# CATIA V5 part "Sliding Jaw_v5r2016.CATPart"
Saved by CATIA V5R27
Part number: Sliding Jaw
Bounding box of the stored display mesh (mm): x -32 to 32, y -16 to 16, z -9 to 36
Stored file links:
  E:\_Deepak\2017_Deepak\CATIA\Resources\Tutorial Files\Tutorials\c13_catia_v5_6r2016_tut\c13tut2\c13tut02.CATParts\Sliding Jaw_v5r2016.CATPart
  C:\Program Files\Dassault Systemes\B09\intel_a\reffiles\standard\MetricThickPitch.txt
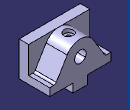
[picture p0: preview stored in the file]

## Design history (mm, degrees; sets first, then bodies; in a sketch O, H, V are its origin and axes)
Body1 (main body)
  Sketch1 on xy-plane, origin (0, 0, 0), H (1, 0, 0), V (0, 1, 0)
    line L1 (-32, -16) -> (32, -16)
    line L2 (32, -16) -> (32, 16)
    line L3 (32, 16) -> (-32, 16)
    line L4 (-32, 16) -> (-32, -16)
    distance H L1 = 16
    distance V L4 = 32
    length L4 = 32
    length L1 = 64
    horizontal: L1 H, L3 H
    vertical: L2 V, L4 V
  Pad1: profile Sketch1, direction (0, 0, 1), length 8
  Sketch2 on face of Pad1, origin (0, -16, 0), H (1, 0, 0), V (0, 0, 1)
    point P1 (-32, 0)
    line L1 (-32, 0) -> (32, 0)
    line L2 (32, 0) -> (32, 36)
    line L3 (32, 36) -> (-32, 36)
    line L4 (-32, 36) -> (-32, 0)
    reference projected line E1 (32, 0) -> (32, 8) from edge of Pad1
    reference projected line E2 (-32, 8) -> (-32, 0) from edge of Pad1
    length L2 = 36
    coincidence: P1 H, L2 E1, L4 E2
    horizontal: L1 H, L3 H
    vertical: L2 V, L4 V
  Pad2: profile Sketch2, direction (0, 1, 0), length 10
  Sketch3 on face of Pad1, origin (0, 16, 0), H (-1, 0, 0), V (0, 0, 1)
    arc A1 centre (0, 20) radius 16 from (13.6777, 28.3018) to (-13.6777, 28.3018) ccw
    point P1 (0, 20)
    reference projected line E1 (-32, 36) -> (32, 36) from edge of Pad2
    line L1 (-26, 8) -> (-13.6777, 28.3018)
    point P2 (-26, 8)
    line L2 (13.6777, 28.3018) -> (26, 8)
    point P3 (26, 8)
    reference projected line E2 (32, 8) -> (-32, 8) from edge of Pad1
    reference projected line E3 (32, 8) -> (-32, 8) from edge of Pad1
    line L3 (-26, 8) -> (26, 8)
    radius A1 = 16
    length L3 = 52
    distance V P3 = 26
    coincidence: P1 V, E2 P2, E3 P3
    tangency: A1 E1, L2 A1, L1 A1
    horizontal: L3 H
  Pad3: profile Sketch3, direction (0, -1, 0), up to the existing solid (limit type 2)
  Fillet1: radius 3, on 2 edges
  Sketch4 on face of Pad1, origin (-2.6964, 16, 22.8197), H (1, 0, 0), V (0, 0, -1)
    point P1 (2.6964, 2.8197)
    reference projected arc E1 centre (2.6964, 2.8197) radius 16 from (-10.9814, -5.4821) to (16.3741, -5.4821) ccw from edge of Pad3
    concentricity: P1 E1
  Hole1: placed by Sketch4, at (0, 16, 20) direction (0, -1, 0), diameter 12, depth 22, V-bottom angle 120
  Sketch5 on face of Pad1, origin (0, 16, 0), H (-1, 0, 0), V (0, 0, 1)
    point P1 (-7.75, 0)
    line L1 (-7.75, 0) -> (7.75, 0)
    line L2 (7.75, 0) -> (7.75, -9)
    line L3 (7.75, -9) -> (-7.75, -9)
    line L4 (-7.75, -9) -> (-7.75, 0)
    distance V L2 = 7.75
    length L3 = 15.5
    length L4 = 9
    coincidence: P1 H
    horizontal: L1 H, L3 H
    vertical: L2 V, L4 V
  Pad4: profile Sketch5, direction (0, -1, 0), length 32
  Sketch6 on face of Pad4, origin (-0.598, -1.2346, -9), H (1, 0, 0), V (0, -1, 0)
    point P1 (0.598, -9.2346)
    reference projected line E1 (8.348, -17.2346) -> (-7.152, -17.2346) from edge of Pad4
    reference projected line E2 (8.348, 14.7654) -> (8.348, -17.2346) from edge of Pad4
    distance P1 E1 = 8
    distance P1 E2 = 7.75
  Hole2: placed by Sketch6, at (0, 8, -9) direction (0, 0, 1), diameter 5, depth 16, V-bottom angle 120, threaded, thread diameter 6, thread depth 16, pitch 1
  RectPattern1: of Hole2, direction 1 instances 2, spacing 16, along edge of Pad4 reversed
  Sketch7 on face of Pad2, origin (-19.6018, -13.7351, 36), H (1, 0, 0), V (0, 1, 0)
    point P1 (19.6018, 17.7351)
    reference intersected line E1 through (19.6018, 0) direction (0, 1) from yz-plane
    reference projected line E2 (51.6018, -2.2649) -> (-12.3982, -2.2649) from edge of Pad2
    distance P1 E2 = 20
    coincidence: E1 P1
  Hole3: placed by Sketch7, at (0, 4, 36) direction (0, 0, -1), diameter 5, depth 16, V-bottom angle 120, counterbore diameter 10, counterbore depth 4, threaded, thread diameter 6, thread depth 11, pitch 1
